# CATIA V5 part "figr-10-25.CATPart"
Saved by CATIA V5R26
Part number: Part1
Bounding box of the stored display mesh (mm): x -92.502 to 25.581, y -200.404 to 0, z 0 to 47.305
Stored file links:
  D:\_Deepak\CATIA\CATIA V5-6R2016_Deepak\Resources\Part files\Partfiles\c10_catia_v5_6r2016_prt\figr-10-25.CATPart
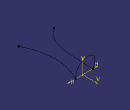
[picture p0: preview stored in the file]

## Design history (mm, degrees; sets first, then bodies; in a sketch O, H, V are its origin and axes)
Set1
  Sketch1 on xy-plane, origin (0, 0, 0), H (1, 0, 0), V (0, 1, 0)
    spline S1 through (-36.6295, 0) (-39.5961, -76.7629) (-56.6868, -154.7631) (-92.5015, -194.2587)
    point P1 (-36.6295, 0)
    coincidence: P1 H
  Sketch2 on xy-plane, origin (0, 0, 0), H (1, 0, 0), V (0, 1, 0)
    spline S1 through (25.5807, 0) (5.5021, -50.6307) (25.5807, -200.404)
    point P1 (25.5807, 0)
    coincidence: P1 H
  Sketch3 on zx-plane, origin (0, 0, 0), H (-1, 0, 0), V (0, 0, 1)
    spline S1 through (-25.5807, 0) (16.4189, 47.2175) (28.9802, 46.33) (36.6295, 0)
    reference projected point E1 (36.6295, 0) from vertex of Sketch1
    reference projected point E2 (-25.5807, 0) from vertex of Sketch2
    point P1 (-25.5807, 0)
    point P2 (36.6295, 0)
    coincidence: P1 H, P2 H, E1 P2, P1 E2
Body1 (main body)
